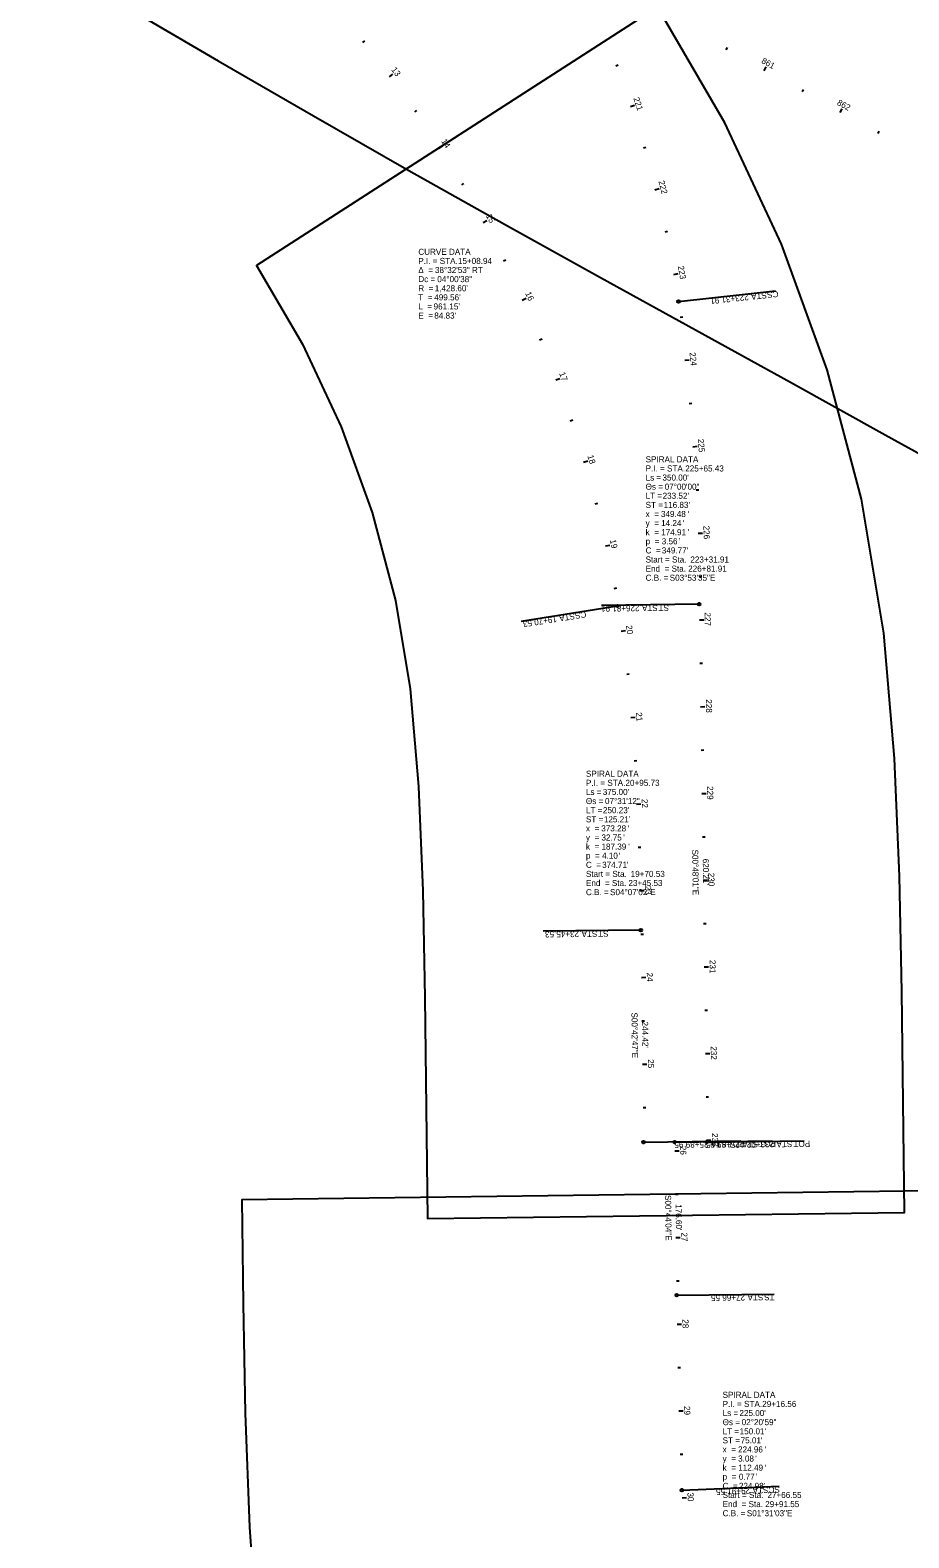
# Model space of a CAD drawing. Extents: x 75725 to 90554, y 518585 to 527848.
# Drawn here: x 86980 to 87993, y 520766 to 522504 of the extents above; entities that cross this region are included whole.
import ezdxf

# ---------------------------------------------------------------- set-up
doc = ezdxf.new("R2010")
doc.units = 0
for name, color, linetype in [('GE_P_Alignment_100_Bearings', 7, 'Continuous'), ('GE_P_Alignment_100_Cardinal_Points', 7, 'Continuous'), ('GE_P_Alignment_100_Curve_Data', 7, 'Continuous'), ('GE_P_Alignment_100_Distances', 7, 'Continuous'), ('GE_P_Alignment_100_Stations', 7, 'Continuous'), ('SH_Named_Boundary', 7, 'Continuous')]:
    doc.layers.add(name, color=color, linetype=linetype)

msp = doc.modelspace()

# ---------------------------------------------------------------- linework, layer by layer
at = {"layer": 'GE_P_Alignment_100_Cardinal_Points'}
for p, q in [((87727.3, 522191.4), (87839.1, 522203.6)), ((87656.9, 521840.4), (87545.8, 521822.6)), ((87751, 521842.4), (87638.5, 521840.9)), ((87683.8, 521466.7), (87571.3, 521465.3)), ((87686.9, 521222.3), (87799.3, 521223.7)), ((87722.9, 521222.3), (87835.4, 521223.7)), ((87759.7, 521222.3), (87872.2, 521223.8)), ((87725.2, 521045.7), (87837.7, 521047.1)), ((87731.1, 520820.8), (87843.5, 520825.4))]:
    msp.add_line(p, q, dxfattribs=at)
for centre in [(87727.3, 522191.4), (87656.9, 521840.4), (87751, 521842.4), (87683.8, 521466.7), (87686.9, 521222.3), (87722.9, 521222.3), (87759.7, 521222.3), (87725.2, 521045.7), (87731.1, 520820.8)]:
    msp.add_circle(centre, 1.5, dxfattribs=at)
at = {"layer": 'GE_P_Alignment_100_Stations'}
for p, q in [((87363.3, 522490.1), (87365.6, 522491.9)), ((87782.3, 522481.8), (87783.7, 522484.4)), ((87393.9, 522450.5), (87397.9, 522453.5)), ((87655, 522463.4), (87657.8, 522464.5)), ((87826.1, 522457.6), (87828.5, 522462)), ((87869.8, 522433.5), (87871.3, 522436.1)), ((87423.1, 522410), (87425.6, 522411.7)), ((87671.7, 522416.3), (87676.5, 522417.9)), ((87913.6, 522409.3), (87916, 522413.7)), ((87957.4, 522385.1), (87958.8, 522387.8)), ((87450.9, 522368.4), (87455.1, 522371.1)), ((87686.8, 522368.6), (87689.6, 522369.5)), ((87477.2, 522325.9), (87479.8, 522327.4)), ((87700.1, 522320.4), (87705, 522321.7)), ((87502, 522282.5), (87506.4, 522284.9)), ((87711.8, 522271.8), (87714.7, 522272.5)), ((87525.3, 522238.2), (87528, 522239.6)), ((87721.8, 522222.8), (87726.7, 522223.7)), ((87547, 522193.2), (87551.6, 522195.3)), ((87729.2, 522173.4), (87732.2, 522173.7)), ((87567.1, 522147.4), (87569.9, 522148.6)), ((87734.5, 522123.7), (87739.5, 522124.2)), ((87585.6, 522101), (87590.3, 522102.7)), ((87739.5, 522073.9), (87742.5, 522074.2)), ((87602.5, 522053.9), (87605.4, 522054.9)), ((87743.9, 522024.1), (87748.9, 522024.5)), ((87617.7, 522006.3), (87622.5, 522007.7)), ((87747.5, 521974.3), (87750.5, 521974.4)), ((87631.3, 521958.1), (87634.2, 521958.9)), ((87750, 521924.3), (87755, 521924.5)), ((87643.1, 521909.6), (87648, 521910.7)), ((87751.1, 521874.3), (87754.1, 521874.4)), ((87653.2, 521860.6), (87656.2, 521861.2)), ((87661.3, 521811.3), (87666.2, 521812)), ((87751.3, 521824.3), (87756.3, 521824.4)), ((87667.5, 521761.7), (87670.5, 521762)), ((87752, 521774.3), (87755, 521774.4)), ((87752.7, 521724.3), (87757.7, 521724.4)), ((87672.3, 521711.9), (87677.3, 521712.3)), ((87753.4, 521674.3), (87756.4, 521674.4)), ((87676, 521662), (87679, 521662.2)), ((87754.1, 521624.4), (87759.1, 521624.4)), ((87678.8, 521612.1), (87683.8, 521612.3)), ((87754.8, 521574.4), (87757.8, 521574.4)), ((87680.9, 521562.2), (87683.9, 521562.3)), ((87755.5, 521524.4), (87760.5, 521524.4)), ((87682.5, 521512.2), (87687.5, 521512.3)), ((87683.9, 521462.2), (87686.9, 521462.2)), ((87756.2, 521474.4), (87759.2, 521474.4)), ((87684.5, 521412.2), (87689.5, 521412.3)), ((87756.9, 521424.4), (87761.9, 521424.4)), ((87685.1, 521362.2), (87688.1, 521362.2)), ((87757.6, 521374.4), (87760.6, 521374.4)), ((87758.3, 521324.4), (87763.3, 521324.5)), ((87685.7, 521312.2), (87690.7, 521312.3)), ((87759, 521274.4), (87762, 521274.4)), ((87686.4, 521262.2), (87689.4, 521262.3)), ((87759.6, 521224.4), (87764.6, 521224.5)), ((87723, 521212.2), (87728, 521212.3)), ((87723.7, 521162.2), (87726.7, 521162.3)), ((87724.3, 521112.2), (87729.3, 521112.3)), ((87725, 521062.2), (87728, 521062.3)), ((87725.6, 521012.2), (87730.6, 521012.3)), ((87726.4, 520962.2), (87729.4, 520962.3)), ((87727.5, 520912.3), (87732.5, 520912.4)), ((87729.2, 520862.3), (87732.2, 520862.4)), ((87731.5, 520812.3), (87736.5, 520812.6))]:
    msp.add_line(p, q, dxfattribs=at)
at = {"layer": 'SH_Named_Boundary'}
for points in [[(87283.5, 523113.2), (86979.6, 522595.9), (87087.4, 522532.6), (87196.5, 522468.8), (87306.2, 522405.4), (87416.2, 522342.7), (87526.6, 522280.6), (87637.3, 522219.1), (87746.8, 522158.7), (87856.2, 522098.3), (87965.6, 522037.9), (88075.1, 521977.5), (88365, 522502.8), (88255.6, 522563.2), (88146.2, 522623.6), (88036.7, 522684), (87927.3, 522744.4), (87819.5, 522804.2), (87712, 522864.7), (87604.8, 522925.8), (87498, 522987.5), (87391.3, 523049.9)], [(87703.2, 522530.7), (87240.7, 522233.1), (87293.6, 522142.3), (87338.1, 522047), (87374, 521948.2), (87401, 521846.6), (87417.8, 521745), (87427.3, 521632.4), (87432.4, 521512), (87434.8, 521389.1), (87436.3, 521261.6), (87437.9, 521134.1), (87987.9, 521141), (87986.3, 521268.4), (87984.7, 521395.9), (87982.1, 521528.9), (87976.4, 521664.6), (87964, 521809), (87938.4, 521963.7), (87898.8, 522112.8), (87846.2, 522257.7), (87780.8, 522397.4)], [(88223.6, 521168.6), (87223.7, 521155.8), (87225.3, 521035.8), (87227.4, 520909.7), (87232.5, 520778.4), (87242.4, 520636.9), (87258.5, 520496), (87280.7, 520355.8), (87309, 520216.8), (87343.4, 520079.2), (87383.8, 519943.2), (87430, 519809.1), (88368, 520155.8), (88336, 520248.6), (88308.1, 520342.7), (88284.3, 520437.9), (88264.7, 520534), (88249.3, 520630.9), (88238.2, 520728.4), (88231.4, 520826.3), (88227.1, 520934.8), (88225.2, 521048.7)]]:
    msp.add_lwpolyline(points, close=True, dxfattribs=at)

# ---------------------------------------------------------------- texts
at = {"layer": 'GE_P_Alignment_100_Bearings'}
for s, rotation, p in [('S00°48\'01"E', 270.8004, (87743, 521559.5)), ('S00°42\'47"E', 270.7129, (87673, 521371.7)), ('S00°44\'04"E', 270.7344, (87711.7, 521161.2))]:
    msp.add_text(s, height=7, rotation=rotation, dxfattribs=at).set_placement(p)
at = {"layer": 'GE_P_Alignment_100_Cardinal_Points'}
for s, rotation, p in [('223+31.91', 186.2261, (87807.8, 522200.1)), (' STA. ', 186.2261, (87831.3, 522202.6)), ('CS', 186.2261, (87842, 522203.8)), ('19+70.53', 189.1309, (87586.3, 521829)), (' STA. ', 189.1309, (87609.7, 521832.7)), ('CS', 189.1309, (87620.3, 521834.4)), ('226+81.91', 180.8004, (87682.3, 521841.4)), (' STA. ', 180.8004, (87705.9, 521841.7)), ('ST', 180.8004, (87716.2, 521841.8)), ('23+45.53', 180.7129, (87612.6, 521465.7)), (' STA. ', 180.7129, (87636.2, 521466)), ('ST', 180.7129, (87646.5, 521466.1)), ('25+89.95', 180.7129, (87761.8, 521223.1)), ('25+89.95', 180.7344, (87797.9, 521223.1)), (' STA. ', 180.7129, (87785.4, 521223.4)), ('POT', 180.7129, (87803.4, 521223.6)), ('233+02.12', 180.8004, (87837.4, 521223.3)), (' STA. ', 180.7344, (87821.5, 521223.4)), ('POT', 180.7344, (87839.5, 521223.7)), (' STA. ', 180.8004, (87861, 521223.6)), ('POT', 180.8004, (87879, 521223.8)), ('27+66.55', 180.7344, (87804, 521046.6)), (' STA. ', 180.7344, (87827.6, 521046.9)), ('TS', 180.7344, (87837.9, 521047)), ('29+91.55', 182.3587, (87809.7, 520823.9)), (' STA. ', 182.3587, (87833.3, 520824.9)), ('SC', 182.3587, (87844, 520825.3))]:
    msp.add_text(s, height=7, rotation=rotation, dxfattribs=at).set_placement(p)
at = {"layer": 'GE_P_Alignment_100_Curve_Data'}
for s, p in [('CURVE DATA', (87427.2, 522245.3)), ('Δ  = ', (87427.2, 522224.3)), ('P.I. = STA. ', (87427.2, 522234.8)), ('38°32\'53" RT', (87446.4, 522224.3)), ('15+08.94', (87472.9, 522234.8)), ('Dc = ', (87427.2, 522213.8)), ('R  = ', (87427.2, 522203.3)), ("1,428.60'", (87446.2, 522203.3)), ('04°00\'38"', (87449.1, 522213.8)), ('T  = ', (87427.2, 522192.8)), ("499.56'", (87445.6, 522192.8)), ('L  = ', (87427.2, 522182.3)), ('E  = ', (87427.2, 522171.8)), ("961.15'", (87444.8, 522182.3)), ("84.83'", (87445.6, 522171.8)), ('SPIRAL DATA', (87689.3, 522006)), ('P.I. = STA. ', (87689.3, 521995.5)), ('225+65.43', (87735, 521995.5)), ('Ls = ', (87689.3, 521985)), ("350.00'", (87708.7, 521985)), ('Θs = ', (87689.3, 521974.5)), ('LT = ', (87689.3, 521964)), ("233.52'", (87708.9, 521964)), ('07°00\'00"', (87711.3, 521974.5)), ('ST = ', (87689.3, 521953.5)), ('349.48', (87707, 521943)), ("116.83'", (87710.1, 521953.5)), ("'", (87737.8, 521943)), ('y  = ', (87689.3, 521932.5)), ('x  = ', (87689.3, 521943)), ('14.24', (87707.2, 521932.5)), ("'", (87732.3, 521932.5)), ('k  = ', (87689.3, 521922)), ('p  = ', (87689.3, 521911.5)), ('174.91', (87707.3, 521922)), ('3.56', (87707.9, 521911.5)), ("'", (87727.5, 521911.5)), ("'", (87738, 521922)), ('Start = Sta. ', (87689.3, 521890.5)), ('C  = ', (87689.3, 521901)), ("349.77'", (87708, 521901)), ('223+31.91', (87740.9, 521890.5)), ('End  = Sta. ', (87689.3, 521880)), ('226+81.91', (87738.4, 521880)), ('C.B. = ', (87689.3, 521869.5)), ('S03°53\'35"E', (87717.1, 521869.5)), ('SPIRAL DATA', (87620.5, 521643.5)), ('P.I. = STA. ', (87620.5, 521633)), ('20+95.73', (87666.1, 521633)), ('Θs = ', (87620.5, 521612)), ('Ls = ', (87620.5, 521622.5)), ("375.00'", (87639.9, 521622.5)), ('07°31\'12"', (87642.5, 521612)), ('LT = ', (87620.5, 521601.5)), ("250.23'", (87640.1, 521601.5)), ('x  = ', (87620.5, 521580.5)), ('ST = ', (87620.5, 521591)), ('373.28', (87638.2, 521580.5)), ("125.21'", (87641.2, 521591)), ("'", (87668.9, 521580.5)), ('y  = ', (87620.5, 521570)), ('k  = ', (87620.5, 521559.5)), ('32.75', (87638.4, 521570)), ('187.39', (87638.4, 521559.5)), ("'", (87663.5, 521570)), ("'", (87669.2, 521559.5)), ('p  = ', (87620.5, 521549)), ('4.10', (87639.1, 521549)), ("'", (87658.6, 521549)), ('C  = ', (87620.5, 521538.5)), ('Start = Sta. ', (87620.5, 521528)), ("374.71'", (87639.2, 521538.5)), ('19+70.53', (87672.1, 521528)), ('End  = Sta. ', (87620.5, 521517.5)), ('23+45.53', (87669.5, 521517.5)), ('C.B. = ', (87620.5, 521507)), ('S04°07\'02"E', (87648.3, 521507)), ('SPIRAL DATA', (87778.1, 520927.4)), ('P.I. = STA. ', (87778.1, 520916.9)), ('29+16.56', (87823.8, 520916.9)), ('Ls = ', (87778.1, 520906.4)), ("225.00'", (87797.5, 520906.4)), ('Θs = ', (87778.1, 520895.9)), ('LT = ', (87778.1, 520885.4)), ("150.01'", (87797.8, 520885.4)), ('02°20\'59"', (87800.1, 520895.9)), ('ST = ', (87778.1, 520874.9)), ('224.96', (87795.9, 520864.4)), ("75.01'", (87798.9, 520874.9)), ("'", (87826.6, 520864.4)), ('x  = ', (87778.1, 520864.4)), ('y  = ', (87778.1, 520853.9)), ('3.08', (87796, 520853.9)), ("'", (87815.6, 520853.9)), ('p  = ', (87778.1, 520832.9)), ('k  = ', (87778.1, 520843.4)), ('112.49', (87796.1, 520843.4)), ('0.77', (87796.8, 520832.9)), ("'", (87816.3, 520832.9)), ("'", (87826.8, 520843.4)), ('C  = ', (87778.1, 520822.4)), ('Start = Sta. ', (87778.1, 520811.9)), ("224.98'", (87796.9, 520822.4)), ('27+66.55', (87829.8, 520811.9)), ('End  = Sta. ', (87778.1, 520801.4)), ('29+91.55', (87827.2, 520801.4)), ('C.B. = ', (87778.1, 520790.9)), ('S01°31\'03"E', (87806, 520790.9))]:
    msp.add_text(s, height=7, dxfattribs=at).set_placement(p)
at = {"layer": 'GE_P_Alignment_100_Distances'}
for s, rotation, p in [("620.21'", 270.8004, (87755.2, 521549)), ("244.42'", 270.7129, (87685.2, 521361.2)), ("176.60'", 270.7344, (87723.9, 521150.7))]:
    msp.add_text(s, height=7, rotation=rotation, dxfattribs=at).set_placement(p)
at = {"layer": 'GE_P_Alignment_100_Stations'}
for s, rotation, p in [('861', 331.102, (87822.2, 522466.9)), ('13', 306.7651, (87395.7, 522458.6)), ('221', 288.5137, (87675.1, 522425.7)), ('862', 331.102, (87909.4, 522418.7)), ('14', 302.7545, (87453.3, 522376.3)), ('222', 284.5137, (87704.1, 522329.9)), ('15', 298.7438, (87504.9, 522290.3)), ('223', 280.5137, (87726.4, 522232)), ('16', 294.7332, (87550.3, 522200.9)), ('224', 275.9612, (87739.9, 522132.5)), ('17', 290.7226, (87589.5, 522108.6)), ('225', 274.6116, (87749.5, 522032.9)), ('18', 286.712, (87622.1, 522013.4)), ('226', 272.1191, (87755.9, 521932.9)), ('19', 282.7013, (87648, 521916.3)), ('227', 270.8004, (87757.4, 521833)), ('20', 277.9953, (87666.7, 521817.7)), ('228', 270.8004, (87758.8, 521732.8)), ('21', 274.8346, (87678.1, 521717.5)), ('229', 270.8004, (87760.2, 521632.7)), ('22', 272.7435, (87684.7, 521617.8)), ('230', 270.8004, (87761.6, 521532.8)), ('23', 271.7218, (87688.6, 521517.8)), ('231', 270.8004, (87763, 521432.3)), ('24', 270.7129, (87690.7, 521417.7)), ('232', 270.8004, (87764.4, 521332.7)), ('25', 270.7129, (87691.9, 521317.8)), ('233', 270.8004, (87765.8, 521232.7)), ('26', 270.7344, (87729.2, 521217.9)), ('27', 270.7344, (87730.5, 521118.1)), ('28', 270.7863, (87731.8, 521017.9)), ('29', 271.5609, (87733.6, 520917.9)), ('30', 272.5352, (87737.5, 520818.2))]:
    msp.add_text(s, height=7, rotation=rotation, dxfattribs=at).set_placement(p)

doc.saveas('drawing.dxf')
